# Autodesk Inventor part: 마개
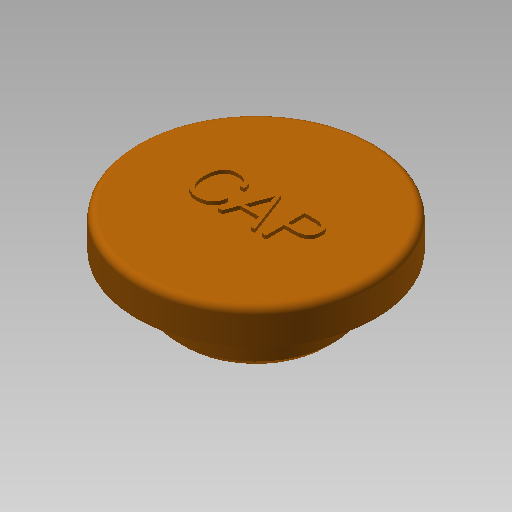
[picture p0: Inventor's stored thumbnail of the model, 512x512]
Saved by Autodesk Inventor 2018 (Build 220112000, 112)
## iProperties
Created: 2018-03
Part Number: 마개
Material: 고무
Document SubType Name: Modeling
Designer: mduedu
Density: 1 g/cm^3
Appearance: 주황색
Author: mduedu
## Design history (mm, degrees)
sketch "스케치1"
  geometry: C1 r 17 at (0, 0); 1 further point
  constraints: 1 centre point, 1 coincident
  dimensions: "d21" = 34 diameter of C1
extrude "돌출1" new body sketch "스케치1" distance "d2" = 6; taper "d3" = 0 deg
fillet "모깎기4" dims "d22" = 1
sketch "스케치6"
  geometry: C1 r 11 at (0, 0); 1 further point
  constraints: 1 centre point, 1 coincident
  dimensions: "d23" = 22 diameter of C1
extrude "돌출5" join sketch "스케치6" distance "d24" = 6; taper "d25" = 0 deg
sketch "스케치7"
  geometry: C1 r 7.5 at (0, 0); 1 further point
  constraints: 1 centre point, 1 coincident
  dimensions: "d26" = 15 diameter of C1
extrude "돌출6" cut sketch "스케치7" distance "d27" = 6; taper "d28" = 0 deg
sketch "스케치8"
  geometry: C1 r 17 at (0, 0) reference; C2 r 14 at (0, 0); 1 further point
  constraints: 1 centre point, 1 coincident
  dimensions: "d37" = 28 diameter of C2
extrude "돌출7" cut sketch "스케치8" distance "d30" = 1; taper "d31" = 0 deg
fillet "모깎기5" dims "d32" = 1
chamfer "모따기2" distance "d33" = 1; stored, may be unused: second distance "d34" = 2, angle "d35" = 45 deg
sketch "스케치5"
  geometry: 2 further points
  constraints: 1 coincident, 1 other
feature "엠보싱1" sketch "스케치5" dims "d19" = 0.5, "d20" = 0
node "솔리드1"
